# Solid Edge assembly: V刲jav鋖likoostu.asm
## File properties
Author: Türk
Template: Iso Assembly.asm
Last saved by: Türk
Revision: 8
Application: Solid Edge
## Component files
ll.par
4k2_R30.par
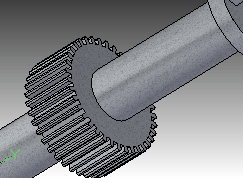
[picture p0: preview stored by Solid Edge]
